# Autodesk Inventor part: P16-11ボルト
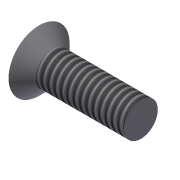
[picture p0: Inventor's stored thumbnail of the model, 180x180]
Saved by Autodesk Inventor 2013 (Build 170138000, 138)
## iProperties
Shininess: 64.0
Length Units: 11269
Angle Units: 11279
Time Units: 11290
Mass Units: 11284
Length Display Precision: 2
Angle Display Precision: 1
Created: 2002-10
Part Number: P16-11ボルト
Document SubType Name: ﾓﾃﾞﾘﾝｸﾞ
Designer: 株式会社富士システム
Stock Number: P3-4ボルト
Density: 1 g/cm^3
Material: 一般
Density: 0.0
Volumn: 0.0
Area: 0.0
PropertySet Name: Model Information
Control State: 0
Master: False
Checked Out: False
Author: 株式会社富士システム
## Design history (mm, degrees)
sketch "ｽｹｯﾁ1"
  geometry: L1 (0, 0)-(0, -6); L2 (0, -6)-(2.677, -3.324); L3 (2.677, -3.324)-(20, -3.323); L4 (20, -3.323)-(20, 0); L5 (20, 0)-(0, 0); 1 further point
  constraints: 10 end point, 2 perpendicular, 1 coincident, 1 parallel, 1 vertical
  dimensions: "d14" = 45 deg angle of L5 L2; "d15" = 12 diameter of L1.end L5; "d16" = 20 distance between parallel lines of L4 L1; "d17" = 6.647 diameter of L3 L5
revolve "回転1" sketch "ｽｹｯﾁ1" stored, may be unused: angle "d5" = 90 deg
feature "ねじ1" dims "d6" = 10, "d7" = 0
sketch "ｽｹｯﾁ2"
  geometry: L1 (0, -6)-(0, 6); L2 (-6, 0)-(6, 0); L3 (-5.999, 0.718)-(-5.957, 0.718); L4 (-5.999, -0.718)-(-5.957, -0.718); L5 (5.957, -0.718)-(5.999, -0.718); L6 (5.957, 0.718)-(5.999, 0.718); L7 (0.718, -5.999)-(0.718, -5.957); L8 (-0.718, -5.999)-(-0.718, -5.957); L9 (-0.7, -3.938)-(-0.7, -0.7); L10 (0.7, -3.938)-(0.7, -0.7); L11 (0.7, 0.7)-(0.7, 3.938); L12 (0.718, 5.957)-(0.718, 5.999); L13 (-0.7, 0.7)-(-0.7, 3.938); L14 (-0.718, 5.957)-(-0.718, 5.999); L15 (-3.938, 0.7)-(-0.7, 0.7); L16 (0.7, 0.7)-(3.938, 0.7); L17 (-3.938, -0.7)-(-0.7, -0.7); L18 (0.7, -0.7)-(3.938, -0.7); A1 r 4 centre (0, 0) between (0.7, 3.938) and (-0.7, 3.938); A2 r 4 centre (0, 0) between (3.938, -0.7) and (3.938, 0.7); A3 r 4 centre (0, 0) between (-3.938, 0.7) and (-3.938, -0.7); A4 r 4 centre (0, 0) between (-0.7, -3.938) and (0.7, -3.938); 1 further point
  constraints: 36 end point, 8 point on circle, 4 centre point, 2 midpoint, 1 coincident, 1 perpendicular, 1 vertical, 13 other
extrude "押し出し1" cut sketch "ｽｹｯﾁ2" distance "d12" = 1; taper "d13" = 0 deg
node "ソリッド1"
node "ソリッド ボディ"
node "サーフェス ボディ"
other parameters: "d8" = 0.7, "d9" = 0.7 (= d8), "d10" = 0.7 (= d8), "d11" = 0.7 (= d8)
